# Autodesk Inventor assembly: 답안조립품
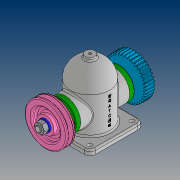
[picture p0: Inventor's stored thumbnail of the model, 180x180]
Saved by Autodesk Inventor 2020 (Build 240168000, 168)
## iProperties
Created: 2021-08
Part Number: 답안조립품
Document SubType Name: Assembly
Designer: PC312-
Author: PC312-
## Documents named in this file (14)
- C:\Users\PC312-\OneDrive - 경남대학교 산학협력단\바탕 화면\710809V1010\답안조립품.iam
- C:\Users\PC312-\OneDrive - 경남대학교 산학협력단\바탕 화면\710809V1010\본체.ipt
- C:\Users\PC312-\OneDrive - 경남대학교 산학협력단\바탕 화면\710809V1010\커버.ipt
- C:\Users\PC312-\OneDrive - 경남대학교 산학협력단\바탕 화면\710809V1010\베어링 6203.ipt
- C:\Users\PC312-\OneDrive - 경남대학교 산학협력단\바탕 화면\710809V1010\축.ipt
- C:\Users\PC312-\OneDrive - 경남대학교 산학협력단\바탕 화면\710809V1010\부시.ipt
- C:\Users\PC312-\OneDrive - 경남대학교 산학협력단\바탕 화면\710809V1010\키 5x5x12.ipt
- C:\Users\PC312-\OneDrive - 경남대학교 산학협력단\바탕 화면\710809V1010\오일 실 26 38 8.ipt
- C:\Users\PC312-\OneDrive - 경남대학교 산학협력단\바탕 화면\710809V1010\볼트 M4.ipt
- C:\Users\PC312-\OneDrive - 경남대학교 산학협력단\바탕 화면\710809V1010\V-벨트풀리.ipt
- V-벨트풀리.ipt
- C:\Users\PC312-\OneDrive - 경남대학교 산학협력단\바탕 화면\710809V1010\와셔 12x24.ipt
- C:\Users\PC312-\OneDrive - 경남대학교 산학협력단\바탕 화면\710809V1010\너트 M12x1.25.ipt
- C:\Users\PC312-\OneDrive - 경남대학교 산학협력단\바탕 화면\710809V1010\스퍼기어.ipt
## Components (1 placed, 1 different names)
1. V-벨트풀리:1
